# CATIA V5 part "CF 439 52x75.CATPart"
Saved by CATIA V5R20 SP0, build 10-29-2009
Part number: CF 439 52x75
Definition: NONE
Nomenclature: CF 439 52x75
Source: Unknown
Description: CF 439 52x75
Bounding box of the stored display mesh (mm): x -39.5 to 39.5, y 0 to 75, z -39.5 to 39.5
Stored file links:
  C:\Users\Utente\Desktop\IO LAVORO\3D X SITO CF\X SITO\CF 439\CF 439 52x75.CATPart
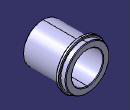
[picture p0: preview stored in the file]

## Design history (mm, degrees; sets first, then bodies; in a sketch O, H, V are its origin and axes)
Body1 "CF 439 52x75" (main body)
  Solid1: solid without history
